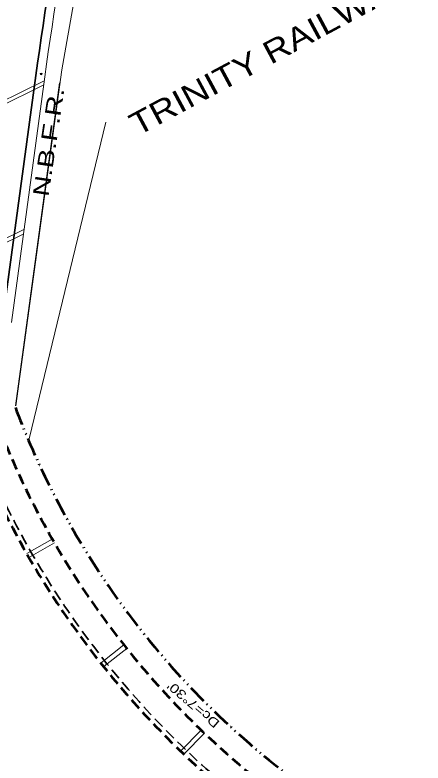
# Model space of a CAD drawing. Extents: x 2354993 to 2372084, y 6966390 to 6990057.
# Drawn here: x 2364914 to 2365274, y 6978519 to 6979180 of the extents above; entities that cross this region are included whole.
import ezdxf

# ---------------------------------------------------------------- set-up
doc = ezdxf.new("R2010")
doc.units = 0
doc.header["$LTSCALE"] = 3.2
doc.header["$PDMODE"] = 32
doc.header["$PDSIZE"] = 1.6
doc.linetypes.add('DASH_DOUBLE_DOT', pattern=[9.2, 5, -1.2, 0.3, -1.2, 0.3, -1.2])
doc.linetypes.add('MEDIUM_DASHED', pattern=[4.5, 3, -1.5])
for name, color, linetype, lineweight in [('12', 7, 'Continuous', 13), ('13', 7, 'Continuous', 13), ('17', 7, 'Continuous', 13), ('23', 7, 'Continuous', 13), ('5', 7, 'Continuous', 35), ('60', 7, 'DASH_DOUBLE_DOT', 53), ('61', 7, 'Continuous', 13), ('9', 7, 'Continuous', 13)]:
    doc.layers.add(name, color=color, linetype=linetype, lineweight=lineweight)

msp = doc.modelspace()

# ---------------------------------------------------------------- linework, layer by layer
at = {"layer": '12'}
for p, q in [((2364886.848, 6979092.839), (2364938.873, 6979118.544)), ((2364887.391, 6979096.536), (2364939.356, 6979122.209)), ((2364862.795, 6978961.889), (2364921.229, 6978990.76)), ((2364861.836, 6978957.555), (2364921.28, 6978986.925))]:
    msp.add_line(p, q, dxfattribs=at)
at = {"layer": '17'}
for p, q in [((2364946.472, 6978716.745), (2364923.897, 6978703.846)), ((2364948.456, 6978713.272), (2364925.882, 6978700.373))]:
    msp.add_line(p, q, dxfattribs=at)
at = {"layer": '23'}
for p, q in [((2364955.036, 6979131.858), (2364989.616, 6979329.308)), ((2364914.348, 6978834.604), (2364955.036, 6979131.858)), ((2364952.982, 6979120.351), (2364913.926, 6978834.661))]:
    msp.add_line(p, q, dxfattribs=at)
at = {"layer": '5'}
msp.add_line((2364902.457, 6978909.452), (2364931.96, 6979126.807), dxfattribs=at)
at = {"layer": '5', "lineweight": 13}
for p, q in [((2364910.384, 6978908.376), (2364939.887, 6979125.731)), ((2364993.883, 6979085.613), (2364926.071, 6978805.28))]:
    msp.add_line(p, q, dxfattribs=at)
for radius, start in [(2892.789, 165.06774), (2844.789, 165.06774), (2892.789, 168.1183)]:
    msp.add_arc((2367758.826, 6978743.101), radius, start, 172.27016, dxfattribs=at)
at = {"layer": '5'}
for radius in [2888.789, 2852.789]:
    msp.add_arc((2367758.826, 6978743.101), radius, 165.06774, 172.27016, dxfattribs=at)
at = {"layer": '5', "linetype": 'MEDIUM_DASHED', "lineweight": 53}
for radius, start in [(755.944, 184.10697), (781.944, 185.55228)]:
    msp.add_arc((2365602.828, 6979091.775), radius, start, 276.23324, dxfattribs=at)
at = {"layer": '5', "linetype": 'MEDIUM_DASHED'}
msp.add_arc((2365602.828, 6979091.775), 777.944, 184.10654, 276.23324, dxfattribs=at)
at = {"layer": '60'}
msp.add_arc((2365602.828, 6979091.775), 735.944, 200.58365, 276.23324, dxfattribs=at)
at = {"layer": '61'}
for p, q in [((2365009.732, 6978623.066), (2364989.781, 6978607.299)), ((2365012.212, 6978619.928), (2364992.261, 6978604.161)), ((2365077.97, 6978547.739), (2365059.918, 6978529.028)), ((2365080.848, 6978544.962), (2365062.796, 6978526.251))]:
    msp.add_line(p, q, dxfattribs=at)
at = {"layer": '9'}
msp.add_arc((2360722.521, 6984327.136), 5729.573, 359.50797, 359.50797, dxfattribs=at)
msp.add_point((2364936.71, 6979128.233), dxfattribs=at)

# ---------------------------------------------------------------- texts
at = {"layer": '13'}
for s, height, rotation, width, p in [('TRINITY RAILWAY EXPRESS', 20, 28.245, 1.2, (2365021.709, 6979072.937)), ('N.B.F.R.', 14, 81.552, 1.35, (2364943.026, 6979019.149))]:
    msp.add_text(s, height=height, rotation=rotation, dxfattribs=dict(at, width=width)).set_placement(p)
at = {"layer": '17', "width": 1.3}
msp.add_text("Dc=7°30'", height=7.999, rotation=139.372, dxfattribs=at).set_placement((2365095.099, 6978554.869))

doc.saveas('drawing.dxf')
